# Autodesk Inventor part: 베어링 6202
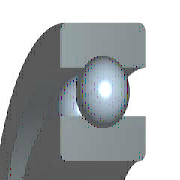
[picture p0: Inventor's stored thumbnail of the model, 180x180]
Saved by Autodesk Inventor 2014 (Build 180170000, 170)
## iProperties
Created: 2015-12
Part Number: 베어링 6202
Material: 강철, 연강
Description: 깊은 그루브 볼 베어링
Document SubType Name: Modeling
Standard: KS B 2023
Designer: mdu
Standards Organization: KS
Language: ko-KR
Size Designation: 6202 - 15 x 35 x 11
Categories: <MemberInstance><Categories><Category DisplayName="샤프트 부품" InternalName="7f7aeb1f-a693-4053-b835-cee3144e0d98" Mnemonic="SHFT"><Category DisplayName="베어링" Inter
Density: 7.86 g/cm^3
Mass: 45.8725 g
Surface Area: 51.5584 cm^2
Volume: 5.83619 cm^3
Appearance: 노란색
Company: 한국ATC센터
IsCustomPart: 1
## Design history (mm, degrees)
sketch "스케치" dims "d0" = 5.2 (= -0.26 x WD + 0.26 x BD)
  geometry: L1 (2.9, 12.5)-(8.1, 12.5); L2 (5.5, 12.5)-(5.5, 9.9); L3 (5.5, 12.5)-(5.5, 15.1); L4 (3.568, 10.76)-(0, 10.76); L5 (0, 7.5)-(11, 7.5); L6 (3.568, 14.24)-(0, 14.24); L7 (0, 17.5)-(11, 17.5); L8 (11, 7.5)-(11, 10.76); L9 (7.432, 10.76)-(11, 10.76); L10 (7.432, 14.24)-(11, 14.24); L11 (11, 17.5)-(11, 14.24); L12 (-1.4, 0)-(8.4, 0) reference; L13 (0, -0.3)-(0, 5.3) reference
  constraints: 22 end point, 4 point on line, 2 collinear, 2 perpendicular, 2 symmetric about line, 1 midpoint, 1 parallel, 14 other
  dimensions: "d9" = 15 diameter of L5 L12 (= WD); "d11" = 35 diameter of L7 L12 (= BD); "d12" = 11 distance between parallel lines of L8 L13 (= KB); "d13" = 21.52 diameter of L9 L12 (= 0.326 x BD + 0.674 x WD)
revolve "본체" stored, may be unused: angle "d6" = 90 deg
revolve "볼" stored, may be unused: angle "d7" = 90 deg
pattern_circular "IDS_ARRAYBALL[SIMPL:T]" dims angle "d3" = 360 deg
body "Solid1"
fillet "모깎기1" dims "d1" = 0.6 (= KRS)
other parameters: "WD" = 15 [user parameter; used in 5 equation terms], "BD" = 35 [user parameter; used in 5 equation terms], "KB" = 11 [user parameter; used in 1 equation term], "KRS" = 0.6 [user parameter; used in 1 equation term], "d4" = 0, "d5" = 0, "d8" = 0, "d14" = 0, "d15" = 0, "BBA" = 0 [user parameter], "BC0" = 3750000 [user parameter], "BC" = 7800000 [user parameter], "BR" = 17.5 (= 0.5 x BD) [user parameter], "WR" = 7.5 (= 0.5 x WD) [user parameter]
